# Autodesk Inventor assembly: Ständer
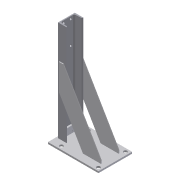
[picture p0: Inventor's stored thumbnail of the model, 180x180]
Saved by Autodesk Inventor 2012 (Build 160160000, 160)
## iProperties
Company: CAD-Verlag
Created: 2004-09
Part Number: Ständer
Document SubType Name: Assembly
Designer: Greiling
Manufacturer: Standard
Standards Organization: Custom
Checked By: Jürgen Kronas
Stock Number: 10-10006
Author: Juergen Kronas
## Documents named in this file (5)
- C:\Daten Vault 2012 Inventor\Kapitel 6\6.2\Anschlag\Ständer.iam
- C:\Daten Vault 2012 Inventor\Kapitel 6\6.2\Anschlag\BreitFlach_Boden.ipt
- C:\Daten Vault 2012 Inventor\Kapitel 6\6.2\Anschlag\Flach_Zyl.ipt
- C:\Daten Vault 2012 Inventor\Kapitel 6\6.2\Anschlag\Blech_Strebe.ipt
- C:\Daten Vault 2012 Inventor\Kapitel 6\6.2\Anschlag\U_100_595.ipt
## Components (5 placed, 4 different names)
1. BreitFlach_Boden:1 — Passend:3, Passend:5, Passend:7, Passend:8, Passend:9, Fluchtend:5
2. Flach_Zyl:1 — Passend:3, Passend:5
3. Blech_Strebe:1 — Passend:7, Fluchtend:3, Fluchtend:4
4. Blech_Strebe:2 — Fluchtend:3, Fluchtend:4
5. DIN 1026  U U 100 - 595:1 — Passend:8, Passend:9, Fluchtend:5
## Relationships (8: Mate 5, Flush 3)
- Passend:3 [Mate]: BreitFlach_Boden:1 ↔ Flach_Zyl:1
- Passend:5 [Mate]: BreitFlach_Boden:1 ↔ Flach_Zyl:1
- Passend:7 [Mate]: BreitFlach_Boden:1 ↔ Blech_Strebe:1
- Fluchtend:3 [Flush]: Blech_Strebe:1 ↔ Blech_Strebe:2
- Fluchtend:4 [Flush]: Blech_Strebe:1 ↔ Blech_Strebe:2
- Passend:8 [Mate]: BreitFlach_Boden:1 ↔ DIN 1026  U U 100 - 595:1
- Passend:9 [Mate]: BreitFlach_Boden:1 ↔ DIN 1026  U U 100 - 595:1
- Fluchtend:5 [Flush]: BreitFlach_Boden:1 ↔ DIN 1026  U U 100 - 595:1
